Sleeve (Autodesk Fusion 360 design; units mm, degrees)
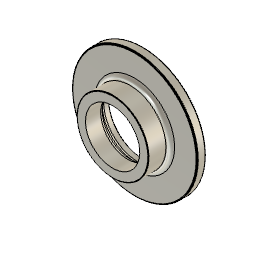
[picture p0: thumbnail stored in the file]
sketch "Sketch1" plane through (0, 0, 0) normal (1, 0, 0) x axis (0, 1, 0)
  line L1 (0, 9.6012) -> (0, 12.7)
  line L2 (5.9182, 9.6012) -> (0, 9.6012)
  line L3 (8.382, 12.065) -> (5.9182, 9.6012)
  line L4 (10.922, 12.065) -> (8.382, 12.065)
  line L5 (10.922, 22.225) -> (10.922, 12.065)
  line L6 (7.747, 22.225) -> (10.922, 22.225)
  line L7 (7.747, 12.7) -> (7.747, 22.225)
  line L8 (0, 12.7) -> (7.747, 12.7)
  line L9 (25.8911, 9.6012) -> (5.9182, 9.6012)
  point P1 (0, 0)
  point P2 (0, 9.6012)
  point P4 (8.382, 12.065)
  point P5 (10.922, 12.065)
  point P6 (10.922, 22.225)
  point P7 (7.747, 22.225)
  point P8 (7.747, 12.7)
  point P9 (0, 12.7)
  vertical L1
  perpendicular L1 L2
  perpendicular L1 L4
  perpendicular L4 L5
  perpendicular L5 L6
  perpendicular L6 L7
  perpendicular L1 L8
  vertical P1 P2
  parallel L2 L9
  dimension "d1" distance P1 L2 = 9.6012 (= "0.375 in + 0.003 in")
  dimension "d2" distance P1 L8 = 12.7
  dimension "d4" angle L3 L9 = 45
  dimension "d5" distance P4 P5 = 2.54
  dimension "d6" distance P6 P7 = 3.175
  dimension "d7" distance P1 L6 = 22.225
  dimension "d8" distance P8 P9 = 7.747
  dimension "d9" distance P1 L4 = 12.065
revolve "Revolve1" sketch "Sketch1" AlongAngle 360
fillet "Fillet1" radius 1.27
fillet "Fillet2" radius 1.524
chamfer "Chamfer2" distance 0.127
chamfer "Chamfer3" distance 0.254
chamfer "Chamfer4" distance 0.127
fillet "Fillet3" radius 0.254
fillet "Fillet4" radius 0.127
fillet "Fillet5" radius 1.27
